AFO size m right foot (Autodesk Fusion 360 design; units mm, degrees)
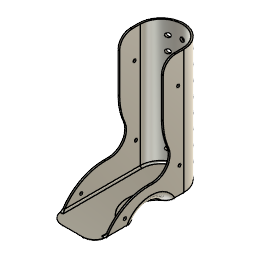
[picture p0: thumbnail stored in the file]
part number: 2025-10-02-12-56-12-317
sketch "Sketch1" plane through (0, 0, 0) normal (0, 0, 1) x axis (1, 0, 0)
  line L1 (-27.4, -108) -> (-27.4, 0)
  line L2 (27.4, -108) -> (-27.4, -108)
  line L3 (27.4, 0) -> (27.4, -108)
  line L4 (-25.4, 0) -> (-25.4, -108)
  line L5 (25.4, 0) -> (25.4, -108)
  line L6 (-25.4, 0) -> (-27.4, 0)
  line L7 (27.4, 0) -> (25.4, 0)
  line L8 (-25.4, -93) -> (-27.4, -93)
  line L9 (-12.4, -108) -> (-12.4, -93)
  line L10 (12.4, -108) -> (12.4, -93)
  line L11 (12.4, -108) -> (-12.4, -108)
  line L12 (27.8748, -92.9999) -> (-13.1252, -92.9999)
  circle C1 centre (0, 0) radius 27.4
  circle C2 centre (0, 0) radius 25.4
  circle C3 centre (-12.4, -93) radius 15
  circle C4 centre (12.4, -93) radius 15
  circle C5 centre (-12.4, -93) radius 13
  circle C6 centre (12.4, -93) radius 13
  point P1 (0, 0)
  point P2 (0, 0)
  point P3 (-27.4, 0)
  point P6 (27.4, 0)
  point P7 (0, 0)
  point P8 (-25.4, 0)
  point P10 (25.4, 0)
  point P11 (25.4, -108)
  point P9 (-25.4, -108)
  point P16 (-27.4, -93)
  point P17 (-25.4, -93)
  point P12 (-12.4, -93)
  point P18 (-12.4, -93)
  point P19 (-12.4, -108)
  point P15 (12.4, -93)
  point P20 (12.4, -93)
  point P21 (12.4, -108)
  coincident P1 P2
  coincident C1 P3
  tangent C1 L1
  vertical L1
  perpendicular L1 L2
  coincident C1 P6
  tangent C1 L3
  perpendicular L2 L3
  coincident P1 P7
  vertical L4
  coincident C2 P8
  vertical L5
  coincident C2 P10
  perpendicular L4 L6
  perpendicular L3 L7
  coincident L2 P11
  coincident L2 P9
  tangent L3 C4
  tangent L1 C3
  tangent L2 C3
  tangent L2 C4
  concentric C3 C5
  tangent L4 C5
  concentric C4 C6
  tangent L5 C6
  coincident C3 P16
  coincident C5 P17
  coincident L4 P17
  perpendicular L4 L8
  coincident P12 P18
  coincident L2 P19
  coincident C3 P19
  perpendicular L2 L9
  coincident P15 P20
  coincident L2 P21
  coincident C4 P21
  perpendicular L2 L10
  perpendicular L3 L12
  dimension "d2" diameter C1 = 54.8 (= "d57 + ( 2 * 2 ) * 1 mm")
  dimension "d4" distance P2 L2 = 108
  dimension "d57" diameter C2 = 50.8
  dimension "d73" diameter C3 = 30
  dimension "d74" diameter C4 = 30
extrude "Extrude1" new body sketch "Sketch1" profile of C1 L1 L3 L4 L5 L6 L7 C3 C4 L8 L12 along normal blind 30
extrude "Extrude2" add sketch "Sketch1" profile of C1 C2 L4 L5 C3 C4 C5 C6 L8 L9 L10 L12 along normal blind 2
extrude "Extrude8" add sketch "Sketch1" profile of L2 C3 C4 L11 along normal blind 2
extrude "Extrude3" add sketch "Sketch1" profile of C1 C2 L6 L7 along normal blind 152.4
work_plane "WorkPlane3" AlongDistance 40
sphere_primitive "SpherePrimitive3" Diameter 55
move_face "MoveFace3"
boundary_fill "BoundaryFill2"
offset_faces "OffsetFaces3" distance 2
shell "Shell5" innerThickness 2
fillet "Fillet31" radius 25
extrude "Extrude15" cut of existing geometry blind -8
work_plane "WorkPlane1" RotateAngle -90
sketch "Sketch2" plane through (27.4, 0, 0) normal (1, 0, 0) x axis (0, 1, 0)
  line L1 (0, 152.4) -> (-25, 152.4)
  line L2 (0, 30) -> (0, 152.4)
  line L3 (-25, 62.4) -> (-25, 152.4)
  line L4 (0, 30) -> (-25, 62.4)
  circle C1 centre (-7, 117.4) radius 1.75
  point P2 (0, 30)
  point P6 (0, 30)
  point P4 (0, 152.4)
  point P7 (0, 152.4)
  point P3 (-25, 152.4)
  point P5 (-25, 62.4)
  point P8 (-7, 117.4)
  horizontal L1
  perpendicular L1 L2
  perpendicular L1 L3
  coincident P2 P6
  coincident P4 P7
  dimension "d25" distance P3 P4 = 25
  dimension "d28" distance P3 P5 = 90
  dimension "d43" diameter C1 = 3.5
  dimension "d45" distance L3 P8 = 18
  dimension "d47" distance L1 P8 = 35
extrude "Extrude11" add sketch "Sketch2" against normal blind 2
mirror "Mirror1" mirrorStitchTolerance 0.1
work_plane "WorkPlane4" AlongDistance 24.25
sketch "Sketch9" plane through (0, 24.25, 0) normal (0, 1, 0) x axis (1, 0, 0)
  circle C1 centre (0, -17) radius 2.5
  circle C2 centre (0, -34) radius 2.5
  circle C3 centre (0, -51) radius 2.5
  circle C4 centre (0, -68) radius 2.5
  circle C5 centre (0, -102) radius 2.5
  circle C6 centre (0, -85) radius 2.5
  circle C7 centre (0, -136) radius 2.5
  circle C8 centre (0, -119) radius 2.5
  point P2 (0, -17)
  point P8 (0, 0)
  point P3 (0, -34)
  point P4 (0, -51)
  point P5 (0, -68)
  point P7 (0, -85)
  point P6 (0, -102)
  dimension "d123" diameter C1 = 5
  dimension "d124" diameter C2 = 5
  dimension "d125" diameter C3 = 5
  dimension "d126" diameter C4 = 5
  dimension "d127" diameter C5 = 5
  dimension "d128" diameter C6 = 5
  dimension "d129" distance P2 P8 = 17
  dimension "d130" distance P2 P3 = 17
  dimension "d131" distance P3 P4 = 17
  dimension "d132" distance P4 P5 = 17 (= "d131")
  dimension "d133" distance P5 P7 = 17 (= "d131")
  dimension "d134" distance P6 P7 = 17 (= "d131")
  dimension "d183" diameter C7 = 5
  dimension "d184" diameter C8 = 5
extrude "Extrude12" cut sketch "Sketch9" along normal blind 70
path_pattern "PathPattern2" PathPatternDelta 82
fillet "Fillet28" radius 60
fillet "Fillet18" radius 80
fillet "Fillet32" radius 10
fillet "Fillet33" radius 10
fillet "Fillet34" radius 20
fillet "Fillet35" radius 15
fillet "Fillet37" radius 5
fillet "Fillet36" radius 2
hole "Hole3" HoleDepth 90 HoleDiameter 3.5 TipAngle 118
hole "Hole4" HoleDepth 90 HoleDiameter 3.5 TipAngle 118
fillet "Fillet44" radius 2
fillet "Fillet45" radius 2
